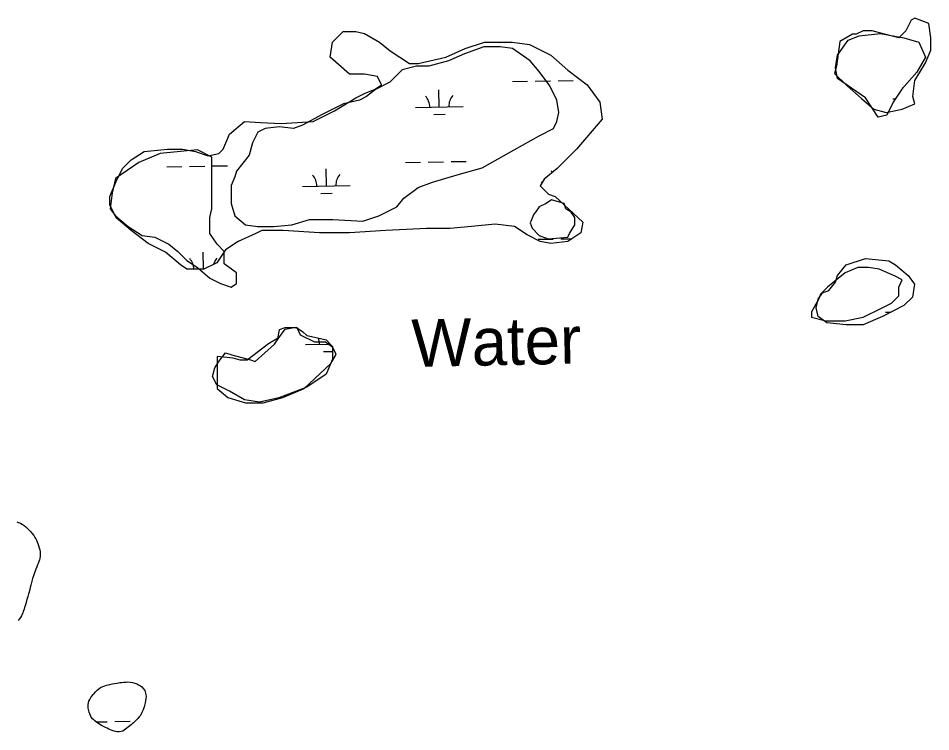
# Model space of a CAD drawing. Extents: x 3914892 to 3953151, y 242587 to 268572.
# Drawn here: x 3947793 to 3949712, y 249954 to 251454 of the extents above; entities that cross this region are included whole.
import ezdxf

# ---------------------------------------------------------------- set-up
doc = ezdxf.new("R2010")
doc.units = 0
for name, color, linetype in [('V-RIVR-IDEN', 7, 'Continuous'), ('V-TOPO-SHOR', 7, 'Continuous'), ('V-WETL-SWMP', 7, 'Continuous')]:
    doc.layers.add(name, color=color, linetype=linetype)

msp = doc.modelspace()

# ---------------------------------------------------------------- linework, layer by layer
at = {"layer": 'V-TOPO-SHOR'}
for points in [[(3949644.3, 251412.8), (3949614.4, 251420.3), (3949588.2, 251427.7), (3949569.4, 251427.7), (3949554.5, 251420.3), (3949547, 251420.3), (3949520.8, 251405.3), (3949517, 251379.1), (3949513.3, 251352.9), (3949509.6, 251337.9), (3949535.8, 251311.7), (3949565.7, 251285.5), (3949591.9, 251263.1), (3949618.1, 251255.6), (3949651.8, 251263.1), (3949678, 251274.3), (3949674.2, 251289.3), (3949678, 251323), (3949696.7, 251352.9), (3949700.4, 251360.4), (3949711.7, 251386.6), (3949711.7, 251412.8), (3949707.9, 251442.7), (3949678, 251453.9), (3949670.5, 251450.2), (3949659.3, 251427.7)], [(3948390.5, 251229.4), (3948371.8, 251221.9), (3948341.8, 251225.6), (3948311.9, 251221.9), (3948296.9, 251214.4), (3948285.7, 251192), (3948278.2, 251165.8), (3948252, 251132.1), (3948248.3, 251120.8), (3948240.8, 251102.1), (3948240.8, 251064.7), (3948248.3, 251038.5), (3948270.7, 251019.8), (3948296.9, 251016), (3948330.6, 251016), (3948368, 251019.8), (3948405.5, 251031), (3948454.1, 251031), (3948517.7, 251027.3), (3948551.4, 251038.5), (3948588.9, 251057.2), (3948603.8, 251075.9), (3948633.8, 251098.4), (3948663.7, 251109.6), (3948716.1, 251124.6), (3948768.5, 251139.6), (3948802.2, 251158.3), (3948835.9, 251177), (3948888.3, 251206.9), (3948918.2, 251221.9), (3948925.7, 251236.9), (3948929.4, 251255.6), (3948925.7, 251281.8), (3948910.7, 251311.7), (3948888.3, 251341.7), (3948869.6, 251364.1), (3948832.1, 251390.3), (3948805.9, 251394.1), (3948772.2, 251394.1), (3948731.1, 251379.1), (3948697.4, 251364.1), (3948656.2, 251352.9), (3948630, 251352.9), (3948600.1, 251345.4), (3948573.9, 251319.2), (3948543.9, 251304.2), (3948525.2, 251289.3), (3948510.3, 251281.8), (3948476.6, 251274.3), (3948431.7, 251251.8)], [(3948169.7, 251177), (3948091.1, 251169.5), (3948046.2, 251150.8), (3947997.5, 251117.1), (3947990, 251087.2), (3947986.3, 251053.5), (3947997.5, 251038.5), (3948023.7, 251016), (3948053.6, 250997.3), (3948079.8, 250993.6), (3948109.8, 250978.6), (3948128.5, 250963.7), (3948147.2, 250944.9), (3948169.7, 250930), (3948195.9, 250907.5), (3948218.3, 250896.3), (3948240.8, 250888.8), (3948252, 250896.3), (3948252, 250918.7), (3948225.8, 250937.5), (3948225.8, 250952.4), (3948225.8, 250963.7), (3948210.8, 250978.6), (3948195.9, 251001.1), (3948195.9, 251034.8), (3948199.6, 251053.5), (3948199.6, 251124.6), (3948199.6, 251162), (3948199.6, 251162)], [(3948940.7, 251064.7), (3948914.5, 251072.2), (3948903.2, 251064.7), (3948888.3, 251057.2), (3948880.8, 251046), (3948877, 251042.2), (3948869.6, 251023.5), (3948873.3, 251012.3), (3948888.3, 250997.3), (3948907, 250989.8), (3948948.2, 250993.6), (3948951.9, 251001.1), (3948963.1, 251019.8), (3948963.1, 251034.8), (3948955.6, 251046), (3948944.4, 251053.5)], [(3949636.8, 250911.3), (3949603.1, 250926.2), (3949580.7, 250930), (3949558.2, 250930), (3949532, 250918.7), (3949513.3, 250903.8), (3949494.6, 250888.8), (3949479.6, 250873.8), (3949475.9, 250862.6), (3949460.9, 250836.4), (3949460.9, 250825.2), (3949490.8, 250817.7), (3949532, 250817.7), (3949569.4, 250825.2), (3949606.9, 250843.9), (3949629.3, 250855.1), (3949644.3, 250870.1), (3949644.3, 250888.8), (3949651.8, 250903.8)], [(3948319.4, 250769), (3948274.5, 250735.3), (3948259.5, 250735.3), (3948244.5, 250739.1), (3948210.8, 250742.8), (3948210.8, 250739.1), (3948210.8, 250709.1), (3948210.8, 250694.2), (3948210.8, 250675.5), (3948233.3, 250656.7), (3948270.7, 250645.5), (3948308.1, 250645.5), (3948349.3, 250656.7), (3948394.2, 250675.5), (3948450.4, 250727.9), (3948461.6, 250746.6), (3948454.1, 250761.5), (3948439.1, 250772.8), (3948416.7, 250772.8), (3948386.7, 250787.7), (3948379.3, 250802.7), (3948353.1, 250802.7), (3948341.8, 250799), (3948338.1, 250780.3)]]:
    msp.add_lwpolyline(points, close=True, dxfattribs=at)
for points in [[(3947790, 250395), (3947793.6, 250393.8), (3947797.6, 250392.1), (3947801.2, 250390.2), (3947805, 250387.5), (3947809.1, 250384.2), (3947811.5, 250381.9), (3947815.3, 250378.3), (3947818.9, 250374.5), (3947821.6, 250371.4), (3947825.4, 250366), (3947827.8, 250362.2), (3947829.6, 250359.2), (3947831.1, 250356.2), (3947832.6, 250352.8), (3947834, 250349.5), (3947835.5, 250345.2), (3947836.9, 250340.6), (3947838, 250336.4), (3947838.6, 250332), (3947838.9, 250327.3), (3947838.8, 250322.6), (3947838.4, 250318.2), (3947837.4, 250314.9), (3947836.4, 250311.4), (3947834.9, 250307.6), (3947833.3, 250304.3), (3947831.8, 250300.6), (3947830.1, 250295.8), (3947828.2, 250291.4), (3947826.8, 250287.8), (3947824.7, 250281.5), (3947822.9, 250275.6), (3947821.4, 250270.1), (3947819.9, 250264.9), (3947819.1, 250261.8), (3947817.9, 250257), (3947816.9, 250253.2), (3947815.5, 250247.5), (3947814.5, 250244), (3947812.8, 250237.8), (3947811, 250231.4), (3947809.3, 250225.6), (3947807.8, 250220.2), (3947806.2, 250215), (3947805.1, 250211.4), (3947803.5, 250206.8), (3947802.2, 250203.4), (3947799.4, 250197.1), (3947797.7, 250193.9), (3947794.7, 250190.2), (3947792.6, 250187.5)], [(3948012.8, 249954.7), (3948009.5, 249954.1), (3948004.9, 249953.7), (3948001.2, 249953.8), (3947997.7, 249954.3), (3947994.4, 249955.1), (3947990.2, 249956.3), (3947987.1, 249957.4), (3947983.4, 249959), (3947979.5, 249960.9), (3947976.4, 249962.5), (3947973.6, 249963.8), (3947970.6, 249965.5), (3947967.8, 249967.1), (3947964.7, 249968.9), (3947961.8, 249971), (3947958, 249973.2), (3947954.2, 249976.4), (3947951.6, 249978.6), (3947949.3, 249980.9), (3947946.4, 249984.3), (3947944.5, 249987.9), (3947943.2, 249991.2), (3947941.9, 249995), (3947940.6, 250000.2), (3947940.2, 250003.4), (3947939.8, 250007.6), (3947940, 250011.1), (3947940.6, 250014.4), (3947941.4, 250017.9), (3947943.1, 250021.7), (3947945.8, 250025.9), (3947947.6, 250028.5), (3947950.3, 250031.9), (3947952.2, 250034.3), (3947955.4, 250037.7), (3947958.6, 250040.9), (3947962, 250043.8), (3947966, 250046.5), (3947970.5, 250048.7), (3947975.1, 250050.4), (3947978.3, 250051.4), (3947982.6, 250052.5), (3947985.7, 250053.3), (3947990.4, 250054.1), (3947995.3, 250055.1), (3948000.6, 250055.9), (3948006.7, 250056.9), (3948011, 250057.1), (3948014, 250057.6), (3948019.5, 250058.1), (3948022.9, 250058.3), (3948028.2, 250058), (3948032.8, 250056.9), (3948037.7, 250055.7), (3948042.1, 250054.1), (3948046, 250052.3), (3948050.1, 250049.9), (3948052.7, 250047.8), (3948055.7, 250044.8), (3948058.7, 250040.4), (3948059.9, 250037.6), (3948061.2, 250032.3), (3948061.6, 250027.9), (3948060.9, 250023.3), (3948060.2, 250018.8), (3948059.5, 250014.8), (3948058.8, 250011.4), (3948057.3, 250006), (3948055.3, 249999.9), (3948053, 249994), (3948049.7, 249988), (3948047.3, 249984.7), (3948044.1, 249981.3), (3948040.7, 249978), (3948037.7, 249975.3), (3948034.9, 249972.5), (3948032.4, 249970.3), (3948030.1, 249968), (3948012.8, 249954.7)]]:
    msp.add_lwpolyline(points, dxfattribs=at)
at = {"layer": 'V-WETL-SWMP'}
for p, q in [((3948831.9, 251320.9), (3948863.9, 251321.4)), ((3948879.9, 251321.7), (3948911.9, 251322.3)), ((3948927.9, 251322.6), (3948959.9, 251323.1)), ((3948975.9, 251323.4), (3948976.4, 251323.4)), ((3948678.2, 251267.4), (3948677.6, 251303.4)), ((3948628.2, 251266.5), (3948728.2, 251268.3)), ((3949631.9, 251284.4), (3949637.4, 251284.5)), ((3948666.5, 251251.7), (3948690.5, 251252.1)), ((3948702.9, 251152.4), (3948734.9, 251152.9)), ((3948105.1, 251141.7), (3948137.1, 251142.2)), ((3948153.1, 251142.5), (3948185.1, 251143.1)), ((3948201.1, 251143.4), (3948233.1, 251143.9)), ((3948440.7, 251101.2), (3948440.1, 251137.2)), ((3948606.9, 251150.6), (3948638.9, 251151.2)), ((3948654.9, 251151.5), (3948686.9, 251152.1)), ((3948390.7, 251100.3), (3948490.7, 251102.1)), ((3948892.5, 251109.3), (3948895.1, 251109.4)), ((3948429, 251085.6), (3948453, 251086)), ((3948885.8, 250989.1), (3948917.8, 250989.7)), ((3948933.8, 250990), (3948957, 250990.4)), ((3948182.4, 250926.2), (3948181.7, 250961.8)), ((3949616.5, 250836), (3949628.4, 250836.2)), ((3948446.6, 250768.6), (3948446.6, 250770.9)), ((3948396.7, 250767.7), (3948448.9, 250768.6)), ((3948434.9, 250753), (3948453.5, 250753.3)), ((3947956.7, 249974.3), (3947980, 249974.7)), ((3947996, 249975), (3948028, 249975.6))]:
    msp.add_line(p, q, dxfattribs=at)
for points in [[(3948413, 251237), (3948458, 251259.5), (3948503, 251286.5), (3948521, 251295.5), (3948543.5, 251304.6), (3948557, 251313.6), (3948548, 251331.6), (3948521, 251336.1), (3948489.5, 251336.1), (3948449, 251372.1), (3948453.5, 251403.6), (3948476, 251426.2), (3948503, 251426.2), (3948521, 251421.7), (3948552.5, 251403.6), (3948575, 251385.6), (3948615.5, 251358.6), (3948633.5, 251358.6), (3948692, 251372.1), (3948732.5, 251390.1), (3948773.1, 251403.6), (3948831.6, 251403.6), (3948867.6, 251399.1), (3948912.6, 251376.6), (3948948.6, 251345.1), (3948989.1, 251313.6), (3949016.1, 251277.5), (3949020.6, 251241.5), (3948966.6, 251178.4), (3948926.1, 251137.9), (3948899.1, 251115.4), (3948890.1, 251101.9), (3948908.1, 251083.8), (3948921.6, 251079.3), (3948980.1, 251025.3), (3948975.6, 251002.8), (3948948.6, 250984.8), (3948912.6, 250980.2), (3948890.1, 250984.8), (3948863.1, 250998.3), (3948836.1, 251016.3), (3948795.6, 251020.8), (3948746, 251016.3), (3948701, 251011.8), (3948651.5, 251011.8), (3948566, 251007.3), (3948489.5, 251002.8), (3948426.5, 251002.8), (3948349.9, 251007.3), (3948304.9, 251007.3), (3948292.3, 251001.5), (3948255.4, 250984.8), (3948228.4, 250966.7), (3948210.4, 250939.7), (3948183.4, 250926.2), (3948147.4, 250926.2), (3948133.9, 250935.2), (3948102.4, 250962.2), (3948066.4, 250980.2), (3948030.4, 251007.3), (3947998.8, 251034.3), (3947985.3, 251061.3), (3947985.3, 251079.3), (3947998.8, 251110.9), (3948012.4, 251137.9), (3948030.4, 251155.9), (3948057.4, 251173.9), (3948106.9, 251178.4), (3948138.4, 251178.4), (3948165.4, 251173.9), (3948192.4, 251164.9), (3948214.9, 251169.4), (3948223.9, 251178.4), (3948237.4, 251210), (3948268.9, 251237), (3948302.2, 251235), (3948345.4, 251232.5)], [(3949601.3, 251246), (3949574.3, 251286.5), (3949515.7, 251327.1), (3949511.2, 251349.6), (3949515.7, 251376.6), (3949538.2, 251408.1), (3949560.8, 251417.2), (3949605.8, 251421.7), (3949655.3, 251412.7), (3949686.8, 251403.6), (3949700.3, 251372.1), (3949682.3, 251340.6), (3949650.8, 251304.6), (3949632.8, 251277.5), (3949619.3, 251250.5)], [(3949533.7, 250935.2), (3949574.3, 250948.7), (3949623.8, 250944.2), (3949637.3, 250935.2), (3949664.3, 250912.7), (3949677.8, 250894.7), (3949673.3, 250867.6), (3949655.3, 250849.6), (3949610.3, 250827.1), (3949569.8, 250809.1), (3949533.7, 250809.1), (3949493.2, 250813.6), (3949475.2, 250827.1), (3949470.7, 250845.1), (3949475.2, 250863.1), (3949484.2, 250876.6), (3949497.7, 250881.2), (3949511.2, 250899.2), (3949515.7, 250912.7)], [(3948281, 250735.4), (3948291.4, 250732.5), (3948331.9, 250768.5), (3948340.9, 250782.1), (3948354.4, 250800.1), (3948376.9, 250804.6), (3948390.5, 250795.6), (3948399.5, 250786.6), (3948422, 250782.1), (3948440, 250777.6), (3948453.5, 250764), (3948453.5, 250737), (3948440, 250705.5), (3948399.5, 250678.5), (3948340.9, 250655.9), (3948300.4, 250646.9), (3948277.4, 250650.2), (3948268.9, 250651.4), (3948237.4, 250669.5), (3948210.4, 250683), (3948201.4, 250701), (3948205.9, 250719), (3948214.9, 250732.5), (3948228.4, 250750.5), (3948241.9, 250746)], [(3948012.8, 249954.7), (3948009.5, 249954.1), (3948004.9, 249953.7), (3948001.2, 249953.8), (3947997.7, 249954.3), (3947994.4, 249955.1), (3947990.2, 249956.3), (3947987.1, 249957.4), (3947983.4, 249959), (3947979.5, 249960.9), (3947976.4, 249962.5), (3947973.6, 249963.8), (3947970.6, 249965.5), (3947967.8, 249967.1), (3947964.7, 249968.9), (3947961.8, 249971), (3947958, 249973.2), (3947954.2, 249976.4), (3947951.6, 249978.6), (3947949.3, 249980.9), (3947946.4, 249984.3), (3947944.5, 249987.9), (3947943.2, 249991.2), (3947941.9, 249995), (3947940.6, 250000.2), (3947940.2, 250003.4), (3947939.8, 250007.6), (3947940, 250011.1), (3947940.6, 250014.4), (3947941.4, 250017.9), (3947943.1, 250021.7), (3947945.8, 250025.9), (3947947.6, 250028.5), (3947950.3, 250031.9), (3947952.2, 250034.3), (3947955.4, 250037.7), (3947958.6, 250040.9), (3947962, 250043.8), (3947966, 250046.5), (3947970.5, 250048.7), (3947975.1, 250050.4), (3947978.3, 250051.4), (3947982.6, 250052.5), (3947985.7, 250053.3), (3947990.4, 250054.1), (3947995.3, 250055.1), (3948000.6, 250055.9), (3948006.7, 250056.9), (3948011, 250057.1), (3948014, 250057.6), (3948019.5, 250058.1), (3948022.9, 250058.3), (3948028.2, 250058), (3948032.8, 250056.9), (3948037.7, 250055.7), (3948042.1, 250054.1), (3948046, 250052.3), (3948050.1, 250049.9), (3948052.7, 250047.8), (3948055.7, 250044.8), (3948058.7, 250040.4), (3948059.9, 250037.6), (3948061.1, 250032.3), (3948061.6, 250027.9), (3948060.9, 250023.3), (3948060.2, 250018.8), (3948059.5, 250014.8), (3948058.8, 250011.4), (3948057.3, 250006), (3948055.3, 249999.9), (3948053, 249994), (3948049.7, 249988), (3948047.3, 249984.7), (3948044.1, 249981.3), (3948040.7, 249978), (3948037.7, 249975.3), (3948034.9, 249972.5), (3948032.4, 249970.3), (3948030.1, 249968)]]:
    msp.add_lwpolyline(points, close=True, dxfattribs=at)
msp.add_lwpolyline([(3947790, 250395), (3947793.6, 250393.8), (3947797.6, 250392.1), (3947801.2, 250390.2), (3947805, 250387.5), (3947809.1, 250384.2), (3947811.5, 250381.9), (3947815.3, 250378.3), (3947818.9, 250374.5), (3947821.6, 250371.4), (3947825.4, 250366), (3947827.8, 250362.2), (3947829.6, 250359.2), (3947831.1, 250356.2), (3947832.6, 250352.8), (3947834, 250349.5), (3947835.5, 250345.2), (3947836.9, 250340.6), (3947838, 250336.4), (3947838.6, 250332), (3947838.9, 250327.3), (3947838.8, 250322.6), (3947838.4, 250318.2), (3947837.4, 250314.9), (3947836.4, 250311.4), (3947834.9, 250307.6), (3947833.3, 250304.3), (3947831.8, 250300.6), (3947830.1, 250295.8), (3947828.2, 250291.4), (3947826.8, 250287.8), (3947824.7, 250281.5), (3947822.9, 250275.6), (3947821.4, 250270.1), (3947819.9, 250264.9), (3947819.1, 250261.8), (3947817.9, 250257), (3947816.9, 250253.2), (3947815.5, 250247.5), (3947814.5, 250244), (3947812.8, 250237.8), (3947811, 250231.4), (3947809.3, 250225.6), (3947807.8, 250220.2), (3947806.2, 250215), (3947805.1, 250211.4), (3947803.5, 250206.8), (3947802.2, 250203.4), (3947799.4, 250197.1), (3947797.7, 250193.9), (3947794.7, 250190.2), (3947792.6, 250187.5)], dxfattribs=at)
for centre, start, end in [((3949626.6, 251284.8), 40.4035, 41.7968), ((3948623, 251266.8), 0.2532, 41.7968), ((3948733.5, 251268.8), 140.2532, 181.7968), ((3948385.5, 251100.7), 0.2532, 41.7968), ((3948495.9, 251102.7), 140.2532, 181.7968), ((3948887.3, 251109.7), 34.6306, 41.7968), ((3948127.1, 250925.2), 1.5439, 41.7968), ((3948237.6, 250927.2), 140.2532, 165.1377), ((3948391.4, 250768.1), 0.2532, 22.4643)]:
    msp.add_arc(centre, 35.2, start, end, dxfattribs=at)

# ---------------------------------------------------------------- texts
at = {"layer": 'V-RIVR-IDEN'}
msp.add_text('Water', height=100, rotation=1.2267, dxfattribs=at).set_placement((3948621, 250720.4))

doc.saveas('drawing.dxf')
